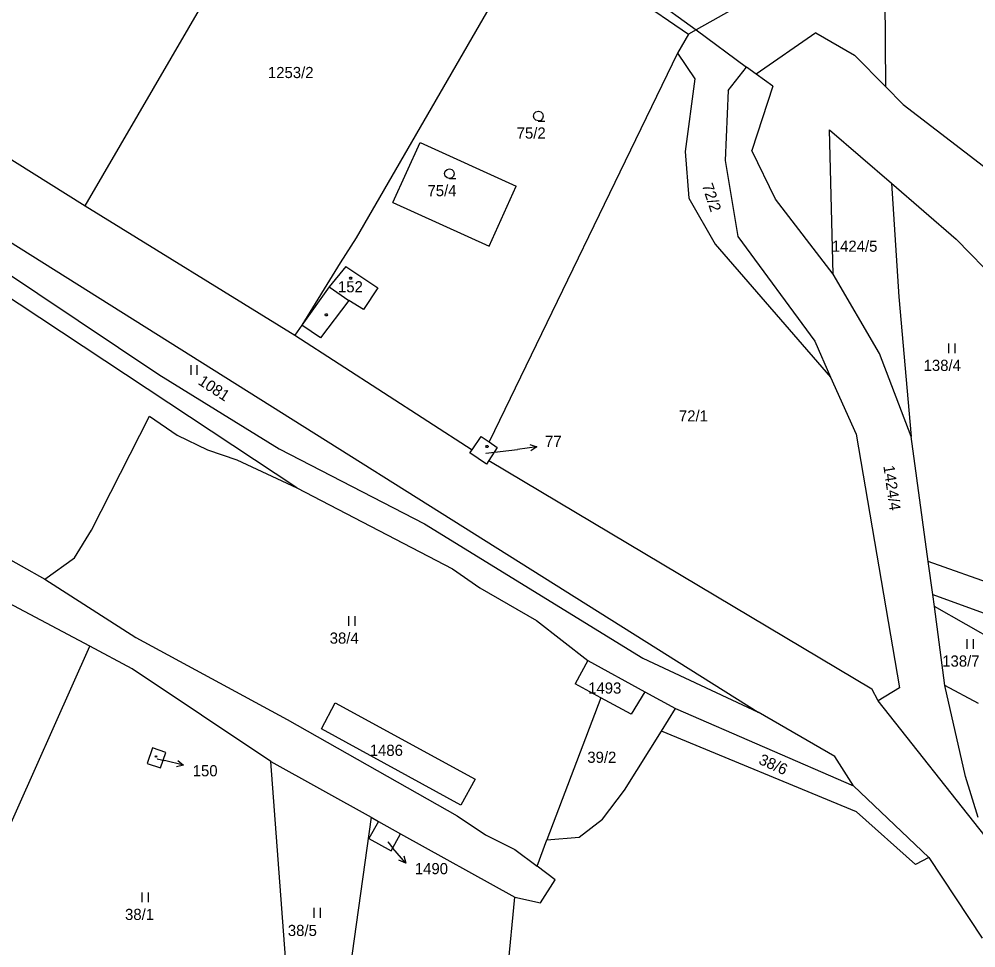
# Model space of a CAD drawing. Extents: x -852001 to -842497, y -1063614 to -1052182.
# Drawn here: x -849422.1 to -849276.2, y -1056165 to -1056023.5 of the extents above; entities that cross this region are included whole.
import ezdxf

# ---------------------------------------------------------------- set-up
doc = ezdxf.new("R2010")
doc.units = 0
for name, color, linetype in [('Default', 7, 'Continuous'), ('KN_HRANICE', 7, 'Continuous'), ('KN_KULTURY', 7, 'Continuous'), ('KN_PARCELY', 7, 'Continuous'), ('KN_SLUCKY', 7, 'Continuous')]:
    doc.layers.add(name, color=color, linetype=linetype)

# ---------------------------------------------------------------- blocks, each defined once
blk = doc.blocks.new('304')
at = {"layer": 'Default'}
blk.add_lwpolyline([(0, 0), (-0.38, 0.1), (-0.65, 0.37), (-0.75, 0.74), (-0.65, 1.11), (-0.38, 1.38), (-0.01, 1.48), (0.36, 1.38), (0.63, 1.11), (0.73, 0.73), (0.63, 0.35), (0.36, 0.08), (-0.02, -0.02), (0.98, -0.02)], dxfattribs=at)
blk = doc.blocks.new('306')
at = {"layer": 'Default'}
for p, q in [((-0.5, 1.5), (-0.5, 0)), ((0.5, 0), (0.5, 1.5))]:
    blk.add_line(p, q, dxfattribs=at)
blk = doc.blocks.new('NAHRADNI_SYMBOL')
at = {"layer": 'Default'}
blk.add_lwpolyline([(0.09, 0.15), (0.18, 0), (0.09, -0.15), (-0.09, -0.15), (-0.18, 0), (-0.09, 0.15), (0.09, 0.15)], dxfattribs=at)
blk = doc.blocks.new('10292')
at = {"layer": 'Default'}
blk.add_line((0, 3), (0, 0), dxfattribs=at)
blk.add_lwpolyline([(-0.5, 2), (0, 3), (0.5, 2)], dxfattribs=at)
blk = doc.blocks.new('402')
at = {"layer": 'Default'}
blk.add_lwpolyline([(0.09, 0.15), (0.18, 0), (0.09, -0.15), (-0.09, -0.15), (-0.18, 0), (-0.09, 0.15), (0.09, 0.15)], dxfattribs=at)

msp = doc.modelspace()

# ---------------------------------------------------------------- linework, layer by layer
at = {"layer": 'KN_HRANICE'}
for p, q in [((-849567.55, -1055954.51), (-849412.04, -1056051.96)), ((-849412.04, -1056051.96), (-849372.63, -1055984.26)), ((-849342.4, -1056007.84), (-849318.86, -1056025.14)), ((-849343.46, -1056009.68), (-849370.71, -1056056.79)), ((-849343.46, -1056009.68), (-849320.03, -1056025.8)), ((-849290.13, -1056018.07), (-849290.02, -1056033.76)), ((-849309.97, -1056020.1), (-849318.86, -1056025.14)), ((-849318.86, -1056025.14), (-849320.03, -1056025.8)), ((-849318.86, -1056025.14), (-849311.18, -1056030.79)), ((-849320.03, -1056025.8), (-849321.71, -1056028.65)), ((-849300.61, -1056025.55), (-849309.7, -1056031.87)), ((-849300.61, -1056025.55), (-849294.73, -1056028.98)), ((-849321.71, -1056028.65), (-849350.45, -1056087.91)), ((-849321.71, -1056028.65), (-849319.06, -1056032.6)), ((-849294.73, -1056028.98), (-849290.02, -1056033.76)), ((-849313.97, -1056034.37), (-849311.18, -1056030.79)), ((-849309.7, -1056031.87), (-849311.18, -1056030.79)), ((-849319.06, -1056032.6), (-849320.53, -1056043.64)), ((-849307.2, -1056033.72), (-849309.7, -1056031.87)), ((-849307.2, -1056033.72), (-849310.38, -1056043.49)), ((-849290.02, -1056033.76), (-849287.32, -1056036.5)), ((-849313.97, -1056034.37), (-849314.46, -1056045.03)), ((-849287.32, -1056036.5), (-849249.28, -1056065.66)), ((-849298.54, -1056040.34), (-849289.1, -1056048.49)), ((-849297.98, -1056062.33), (-849298.54, -1056040.34)), ((-849447.97, -1056042.09), (-849309.42, -1056129.11)), ((-849365.1, -1056051.42), (-849360.97, -1056042.31)), ((-849360.97, -1056042.31), (-849346.31, -1056048.96)), ((-849320.53, -1056043.64), (-849320, -1056050.75)), ((-849306.79, -1056050.91), (-849310.38, -1056043.49)), ((-849314.46, -1056045.03), (-849312.52, -1056056.62)), ((-849447.99, -1056046.05), (-849400.8, -1056077.65)), ((-849289.1, -1056048.49), (-849287.99, -1056065.79)), ((-849289.1, -1056048.49), (-849279.23, -1056057.01)), ((-849350.44, -1056058.07), (-849346.31, -1056048.96)), ((-849365.1, -1056051.42), (-849350.44, -1056058.07)), ((-849320, -1056050.75), (-849315.99, -1056057.76)), ((-849297.98, -1056062.33), (-849306.79, -1056050.91)), ((-849412.04, -1056051.96), (-849380.09, -1056071.64)), ((-849379.78, -1056094.91), (-849440.78, -1056054.56)), ((-849370.71, -1056056.79), (-849373.13, -1056060.63)), ((-849312.52, -1056056.62), (-849300.79, -1056072.57)), ((-849279.23, -1056057.01), (-849266.21, -1056070.35)), ((-849315.99, -1056057.76), (-849298.41, -1056078.07)), ((-849373.13, -1056060.63), (-849379.02, -1056070.11)), ((-849372.27, -1056061.2), (-849374.84, -1056064.26)), ((-849372.27, -1056061.2), (-849367.43, -1056064.42)), ((-849290.92, -1056074.46), (-849297.98, -1056062.33)), ((-849374.84, -1056064.26), (-849379.02, -1056070.11)), ((-849367.43, -1056064.42), (-849369.6, -1056067.76)), ((-849287.99, -1056065.79), (-849286.11, -1056087.07)), ((-849371.84, -1056066.36), (-849376.17, -1056072.03)), ((-849369.6, -1056067.76), (-849371.84, -1056066.36)), ((-849379.02, -1056070.11), (-849380.09, -1056071.64)), ((-849376.17, -1056072.03), (-849379.02, -1056070.11)), ((-849380.09, -1056071.64), (-849353.05, -1056089.1)), ((-849300.79, -1056072.57), (-849298.41, -1056078.07)), ((-849286.11, -1056087.07), (-849290.92, -1056074.46)), ((-849400.8, -1056077.65), (-849382.48, -1056088.99)), ((-849298.41, -1056078.07), (-849294.47, -1056086.71)), ((-849411.05, -1056101.37), (-849402.23, -1056083.97)), ((-849402.23, -1056083.97), (-849397.99, -1056086.9)), ((-849397.99, -1056086.9), (-849393.39, -1056089.1)), ((-849353.05, -1056089.1), (-849351.67, -1056087.07)), ((-849351.67, -1056087.07), (-849350.45, -1056087.91)), ((-849350.45, -1056087.91), (-849349.23, -1056088.76)), ((-849294.47, -1056086.71), (-849287.88, -1056125.38)), ((-849283.48, -1056106.16), (-849286.11, -1056087.07)), ((-849393.39, -1056089.1), (-849388.9, -1056090.64)), ((-849382.48, -1056088.99), (-849360.29, -1056100.39)), ((-849353.38, -1056089.59), (-849353.05, -1056089.1)), ((-849349.23, -1056088.76), (-849350.5, -1056090.75)), ((-849388.9, -1056090.64), (-849379.78, -1056094.91)), ((-849350.85, -1056091.31), (-849353.38, -1056089.59)), ((-849350.5, -1056090.75), (-849350.85, -1056091.31)), ((-849350.5, -1056090.75), (-849292.1, -1056125.54)), ((-849443.99, -1056094.41), (-849418.2, -1056108.82)), ((-849379.78, -1056094.91), (-849356.05, -1056107.25)), ((-849411.33, -1056119.03), (-849445.63, -1056100.85)), ((-849360.29, -1056100.39), (-849326.99, -1056120.89)), ((-849413.64, -1056105.56), (-849411.05, -1056101.37)), ((-849418.2, -1056108.82), (-849413.64, -1056105.56)), ((-849242.85, -1056120.56), (-849283.48, -1056106.16)), ((-849282.78, -1056111.19), (-849283.48, -1056106.16)), ((-849356.05, -1056107.25), (-849351.87, -1056110.15)), ((-849418.2, -1056108.82), (-849404.3, -1056117.7)), ((-849351.87, -1056110.15), (-849343.23, -1056115.14)), ((-849282.53, -1056112.97), (-849282.78, -1056111.19)), ((-849282.78, -1056111.19), (-849239.16, -1056126.97)), ((-849270.99, -1056119.57), (-849282.53, -1056112.97)), ((-849280.97, -1056125.03), (-849282.53, -1056112.97)), ((-849343.23, -1056115.14), (-849335.37, -1056121.22)), ((-849404.3, -1056117.7), (-849381.24, -1056130.24)), ((-849425.04, -1056149.71), (-849411.33, -1056119.03)), ((-849404.87, -1056122.47), (-849411.33, -1056119.03)), ((-849335.37, -1056121.22), (-849337.34, -1056124.78)), ((-849335.37, -1056121.22), (-849326.68, -1056125.99)), ((-849326.99, -1056120.89), (-849309.42, -1056129.11)), ((-849383.75, -1056136.63), (-849404.87, -1056122.47)), ((-849333.4, -1056126.91), (-849337.34, -1056124.78)), ((-849291.12, -1056127.37), (-849292.1, -1056125.54)), ((-849287.88, -1056125.38), (-849291.12, -1056127.37)), ((-849277.82, -1056138.91), (-849280.97, -1056125.03)), ((-849275.8, -1056127.79), (-849280.97, -1056125.03)), ((-849333.4, -1056126.91), (-849341.62, -1056148.56)), ((-849328.77, -1056129.41), (-849333.4, -1056126.91)), ((-849326.68, -1056125.99), (-849328.77, -1056129.41)), ((-849326.68, -1056125.99), (-849322, -1056128.52)), ((-849274.83, -1056148), (-849291.12, -1056127.37)), ((-849375.98, -1056131.66), (-849373.93, -1056127.66)), ((-849373.93, -1056127.66), (-849352.58, -1056139.31)), ((-849324.16, -1056131.97), (-849322, -1056128.52)), ((-849322, -1056128.52), (-849294.9, -1056140.33)), ((-849381.24, -1056130.24), (-849355.34, -1056144.91)), ((-849297.73, -1056135.84), (-849309.42, -1056129.11)), ((-849354.75, -1056143.29), (-849375.98, -1056131.66)), ((-849329.78, -1056140.97), (-849324.16, -1056131.97)), ((-849294.45, -1056144.27), (-849324.16, -1056131.97)), ((-849401.75, -1056134.54), (-849402.56, -1056136.9)), ((-849399.74, -1056135.23), (-849401.75, -1056134.54)), ((-849400.53, -1056137.6), (-849399.74, -1056135.23)), ((-849294.9, -1056140.33), (-849297.73, -1056135.84)), ((-849402.56, -1056136.9), (-849400.53, -1056137.6)), ((-849381.49, -1056166.49), (-849383.75, -1056136.63)), ((-849383.75, -1056136.63), (-849368.45, -1056145.12)), ((-849275.85, -1056145.17), (-849277.82, -1056138.91)), ((-849352.58, -1056139.31), (-849354.75, -1056143.29)), ((-849294.9, -1056140.33), (-849283.41, -1056151.23)), ((-849333.15, -1056145.41), (-849329.78, -1056140.97)), ((-849355.34, -1056144.91), (-849351.01, -1056147.79)), ((-849285.45, -1056152.29), (-849294.45, -1056144.27)), ((-849368.45, -1056145.12), (-849372.11, -1056171.57)), ((-849367.33, -1056145.75), (-849368.78, -1056148.36)), ((-849368.45, -1056145.12), (-849367.33, -1056145.75)), ((-849367.33, -1056145.75), (-849363.95, -1056147.62)), ((-849336.73, -1056148.17), (-849333.15, -1056145.41)), ((-849365.39, -1056150.22), (-849363.95, -1056147.62)), ((-849363.95, -1056147.62), (-849346.5, -1056157.31)), ((-849351.01, -1056147.79), (-849346.52, -1056150.01)), ((-849368.78, -1056148.36), (-849365.39, -1056150.22)), ((-849343.13, -1056152.55), (-849341.62, -1056148.56)), ((-849341.62, -1056148.56), (-849336.73, -1056148.17)), ((-849346.52, -1056150.01), (-849343.13, -1056152.55)), ((-849283.41, -1056151.23), (-849285.45, -1056152.29)), ((-849283.41, -1056151.23), (-849275.26, -1056163.54)), ((-849340.35, -1056154.64), (-849343.13, -1056152.55)), ((-849342.62, -1056158.13), (-849340.35, -1056154.64)), ((-849348.36, -1056176.35), (-849346.5, -1056157.31)), ((-849346.5, -1056157.31), (-849342.62, -1056158.13))]:
    msp.add_line(p, q, dxfattribs=at)
at = {"layer": 'KN_PARCELY'}
for p, q in [((-849350.93, -1056089.65), (-849346.14, -1056089.05)), ((-849401.06, -1056136.2), (-849399.95, -1056136.47)), ((-849365.91, -1056148.88), (-849365.11, -1056149.81))]:
    msp.add_line(p, q, dxfattribs=at)
at = {"layer": 'KN_SLUCKY'}
msp.add_line((-849374.84, -1056064.26), (-849371.84, -1056066.36), dxfattribs=at)

# ---------------------------------------------------------------- block references
at = {"layer": 'KN_KULTURY'}
for name, p in [('304', (-849342.92, -1056038.99)), ('304', (-849356.48, -1056047.77)), ('402', (-849371.56, -1056062.98)), ('402', (-849375.28, -1056068.54)), ('306', (-849279.9, -1056074.4)), ('306', (-849395.44, -1056077.71)), ('402', (-849350.75, -1056088.62)), ('306', (-849371.39, -1056115.96)), ('306', (-849277.1, -1056119.46)), ('306', (-849402.88, -1056158.07)), ('306', (-849376.66, -1056160.42))]:
    msp.add_blockref(name, p, dxfattribs=at)
at = {"layer": 'KN_KULTURY', "xscale": 0.67, "yscale": 0.67}
msp.add_blockref('NAHRADNI_SYMBOL', (-849401.24, -1056135.85), dxfattribs=at)
at = {"layer": 'KN_PARCELY'}
for p, rotation in [((-849346.14, -1056089.05), -82.86031400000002), ((-849399.95, -1056136.47), -103.54409100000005), ((-849365.11, -1056149.81), -139.41124900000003)]:
    msp.add_blockref('10292', p, dxfattribs=dict(at, rotation=rotation))

# ---------------------------------------------------------------- texts
for s, height, p in [('1253/2', 1.7, (-849384.17, -1056032.47)), ('75/2', 1.7, (-849346.24, -1056041.69)), ('75/4', 1.7, (-849359.84, -1056050.47)), ('1424/5', 1.7, (-849298.19, -1056058.94)), ('152', 1.7, (-849373.49, -1056065.12)), ('138/4', 1.7, (-849284.19, -1056077.1)), ('72/1', 1.7, (-849321.5, -1056084.8)), ('77', 1.7, (-849341.92, -1056088.68)), ('77', 0.1, (-849351.03, -1056089.65)), ('38/4', 1.7, (-849374.75, -1056118.66)), ('138/7', 1.7, (-849281.35, -1056122.16)), ('1493', 1.7, (-849335.34, -1056126.27)), ('1486', 1.7, (-849368.64, -1056135.76)), ('150', 0.1, (-849401.21, -1056136.2)), ('39/2', 1.7, (-849335.47, -1056136.82)), ('150', 1.7, (-849395.64, -1056138.87)), ('1490', 0.1, (-849366.11, -1056148.88)), ('1490', 1.7, (-849361.77, -1056153.79)), ('38/1', 1.7, (-849405.96, -1056160.77)), ('38/5', 1.7, (-849381.13, -1056163.21))]:
    msp.add_text(s, height=height, dxfattribs=at).set_placement(p)
for s, rotation, p in [('72/2', 288.484, (-849318.02, -1056048.82)), ('1081', 326.758, (-849394.95, -1056079.04)), ('1424/4', 278.228, (-849290.34, -1056091.59)), ('38/6', 336.04, (-849309.47, -1056136.93))]:
    msp.add_text(s, height=1.7, rotation=rotation, dxfattribs=at).set_placement(p)

doc.saveas('drawing.dxf')
